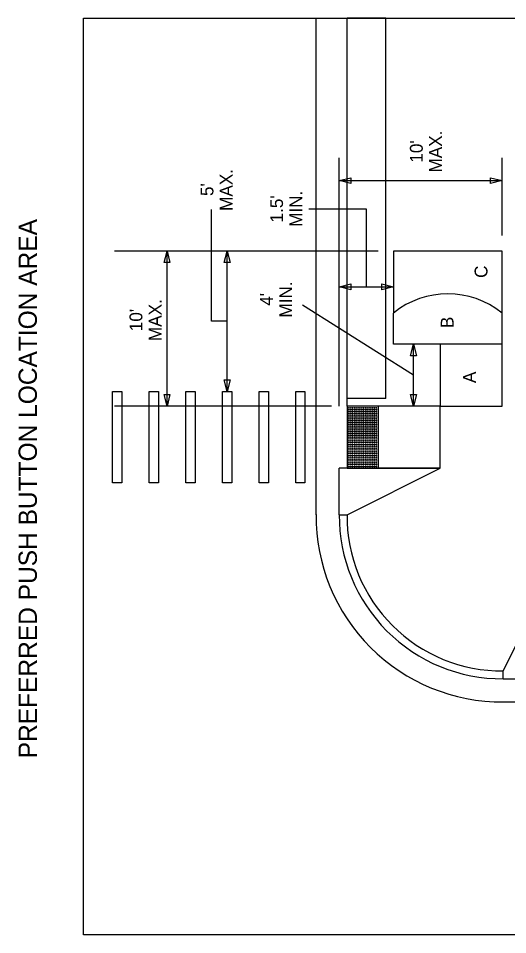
# Model space of a CAD drawing. Extents: x 610558 to 611161, y 419194 to 420064.
# Drawn here: x 610651.8 to 610812, y 419194 to 419494 of the extents above; entities that cross this region are included whole.
import ezdxf

# ---------------------------------------------------------------- set-up
doc = ezdxf.new("R2010")
doc.units = 0
doc.layers.add('Level 10', color=7, linetype='Continuous')

msp = doc.modelspace()

# ---------------------------------------------------------------- linework, layer by layer
at = {"layer": 'Level 10'}
for p, q in [((610673.08, 419194.01), (610673.08, 419494.01)), ((610673.08, 419494.01), (610962.92, 419494.01)), ((610749.26, 419331.49), (610749.26, 419494.01)), ((610759.42, 419367.04), (610759.42, 419494.01)), ((610772.11, 419494.01), (610759.42, 419494.01)), ((610772.11, 419369.58), (610772.11, 419494.01)), ((610756.88, 419367.04), (610756.88, 419448.3)), ((610810.2, 419422.91), (610810.2, 419448.3)), ((610756.88, 419440.88), (610810.2, 419440.88)), ((610769.57, 419417.83), (610683.24, 419417.83)), ((610700.47, 419367.04), (610700.47, 419417.83)), ((610720.15, 419371.89), (610720.15, 419417.83)), ((610810.2, 419397.52), (610810.2, 419417.83)), ((610756.88, 419406.09), (610774.65, 419406.09)), ((610781.18, 419377.2), (610744.87, 419400.08)), ((610774.65, 419387.36), (610774.65, 419397.52)), ((610810.2, 419387.36), (610810.2, 419397.52)), ((610810.2, 419387.36), (610774.65, 419387.36)), ((610781.18, 419367.04), (610781.18, 419387.36)), ((610754.34, 419367.04), (610683.24, 419367.04)), ((610772.11, 419369.58), (610759.42, 419369.58)), ((610789.89, 419367.04), (610759.42, 419367.04)), ((610759.42, 419367.04), (610759.42, 419346.73)), ((610769.57, 419367.04), (610769.57, 419346.73)), ((610789.89, 419346.73), (610789.89, 419367.04)), ((610789.89, 419346.73), (610756.88, 419346.73)), ((610756.88, 419331.49), (610756.88, 419346.73)), ((610759.42, 419346.73), (610789.89, 419346.73)), ((610759.42, 419331.49), (610789.89, 419346.73)), ((610756.88, 419331.49), (610759.42, 419331.49)), ((610810.56, 419280.35), (610825.8, 419310.82)), ((610810.56, 419277.81), (610810.56, 419280.35)), ((610810.56, 419277.81), (610825.8, 419277.81)), ((610810.56, 419270.19), (610861.35, 419270.19)), ((610962.92, 419194.01), (610673.08, 419194.01))]:
    msp.add_line(p, q, dxfattribs=at)
for points in [[(610760.69, 419439.93), (610756.88, 419440.88), (610760.69, 419441.83)], [(610806.39, 419441.83), (610810.2, 419440.88), (610806.39, 419439.93)], [(610699.52, 419414.02), (610700.47, 419417.83), (610701.43, 419414.02)], [(610719.2, 419414.02), (610720.15, 419417.83), (610721.1, 419414.02)], [(610760.69, 419405.14), (610756.88, 419406.09), (610760.69, 419407.04)], [(610770.84, 419407.04), (610774.65, 419406.09), (610770.84, 419405.14)], [(610780.22, 419383.55), (610781.18, 419387.36), (610782.13, 419383.55)], [(610789.89, 419367.04), (610810.2, 419367.04), (610810.2, 419387.36), (610789.89, 419387.36)], [(610721.1, 419375.7), (610720.15, 419371.89), (610719.2, 419375.7)], [(610682.65, 419371.89), (610685.65, 419371.89), (610685.65, 419341.89), (610682.65, 419341.89)], [(610694.65, 419371.89), (610697.65, 419371.89), (610697.65, 419341.89), (610694.65, 419341.89)], [(610701.43, 419370.85), (610700.47, 419367.04), (610699.52, 419370.85)], [(610706.65, 419371.89), (610709.65, 419371.89), (610709.65, 419341.89), (610706.65, 419341.89)], [(610718.65, 419371.89), (610721.65, 419371.89), (610721.65, 419341.89), (610718.65, 419341.89)], [(610730.65, 419371.89), (610733.65, 419371.89), (610733.65, 419341.89), (610730.65, 419341.89)], [(610742.65, 419371.89), (610745.65, 419371.89), (610745.65, 419341.89), (610742.65, 419341.89)], [(610782.13, 419370.85), (610781.18, 419367.04), (610780.22, 419370.85)]]:
    msp.add_lwpolyline(points, close=True, dxfattribs=at)
for points in [[(610720.15, 419394.86), (610715.07, 419394.86), (610715.07, 419431.4)], [(610765.76, 419406.09), (610765.76, 419431.48), (610746.86, 419431.48)], [(610810.2, 419417.83), (610774.65, 419417.83), (610774.65, 419397.52)]]:
    msp.add_lwpolyline(points, dxfattribs=at)
for centre in [(610760.02, 419366.49), (610760.02, 419365.89), (610760.02, 419365.29), (610760.02, 419364.69), (610760.02, 419364.09), (610760.62, 419366.49), (610760.62, 419365.89), (610760.62, 419365.29), (610760.62, 419364.69), (610760.62, 419364.09), (610761.22, 419366.49), (610761.22, 419365.89), (610761.22, 419365.29), (610761.22, 419364.69), (610761.22, 419364.09), (610761.82, 419366.49), (610761.82, 419365.89), (610761.82, 419365.29), (610761.82, 419364.69), (610761.82, 419364.09), (610762.42, 419366.49), (610762.42, 419365.89), (610762.42, 419365.29), (610762.42, 419364.69), (610762.42, 419364.09), (610763.02, 419366.49), (610763.02, 419365.89), (610763.02, 419365.29), (610763.02, 419364.69), (610763.02, 419364.09), (610763.62, 419366.49), (610763.62, 419365.89), (610763.62, 419365.29), (610763.62, 419364.69), (610763.62, 419364.09), (610764.22, 419366.49), (610764.22, 419365.89), (610764.22, 419365.29), (610764.22, 419364.69), (610764.22, 419364.09), (610764.82, 419366.49), (610764.82, 419365.89), (610764.82, 419365.29), (610764.82, 419364.69), (610764.82, 419364.09), (610765.42, 419366.49), (610765.42, 419365.89), (610765.42, 419365.29), (610765.42, 419364.69), (610765.42, 419364.09), (610766.02, 419366.49), (610766.02, 419365.89), (610766.02, 419365.29), (610766.02, 419364.69), (610766.02, 419364.09), (610766.62, 419366.49), (610766.62, 419365.89), (610766.62, 419365.29), (610766.62, 419364.69), (610766.62, 419364.09), (610767.22, 419366.49), (610767.22, 419365.89), (610767.22, 419365.29), (610767.22, 419364.69), (610767.22, 419364.09), (610767.82, 419366.49), (610767.82, 419365.89), (610767.82, 419365.29), (610767.82, 419364.69), (610767.82, 419364.09), (610768.42, 419366.49), (610768.42, 419365.89), (610768.42, 419365.29), (610768.42, 419364.69), (610768.42, 419364.09), (610769.02, 419366.49), (610769.02, 419365.89), (610769.02, 419365.29), (610769.02, 419364.69), (610769.02, 419364.09), (610760.02, 419363.49), (610760.02, 419362.89), (610760.02, 419362.29), (610760.02, 419361.69), (610760.02, 419361.09), (610760.62, 419363.49), (610760.62, 419362.89), (610760.62, 419362.29), (610760.62, 419361.69), (610760.62, 419361.09), (610761.22, 419363.49), (610761.22, 419362.89), (610761.22, 419362.29), (610761.22, 419361.69), (610761.22, 419361.09), (610761.82, 419363.49), (610761.82, 419362.89), (610761.82, 419362.29), (610761.82, 419361.69), (610761.82, 419361.09), (610762.42, 419363.49), (610762.42, 419362.89), (610762.42, 419362.29), (610762.42, 419361.69), (610762.42, 419361.09), (610763.02, 419363.49), (610763.02, 419362.89), (610763.02, 419362.29), (610763.02, 419361.69), (610763.02, 419361.09), (610763.62, 419363.49), (610763.62, 419362.89), (610763.62, 419362.29), (610763.62, 419361.69), (610763.62, 419361.09), (610764.22, 419363.49), (610764.22, 419362.89), (610764.22, 419362.29), (610764.22, 419361.69), (610764.22, 419361.09), (610764.82, 419363.49), (610764.82, 419362.89), (610764.82, 419362.29), (610764.82, 419361.69), (610764.82, 419361.09), (610765.42, 419363.49), (610765.42, 419362.89), (610765.42, 419362.29), (610765.42, 419361.69), (610765.42, 419361.09), (610766.02, 419363.49), (610766.02, 419362.89), (610766.02, 419362.29), (610766.02, 419361.69), (610766.02, 419361.09), (610766.62, 419363.49), (610766.62, 419362.89), (610766.62, 419362.29), (610766.62, 419361.69), (610766.62, 419361.09), (610767.22, 419363.49), (610767.22, 419362.89), (610767.22, 419362.29), (610767.22, 419361.69), (610767.22, 419361.09), (610767.82, 419363.49), (610767.82, 419362.89), (610767.82, 419362.29), (610767.82, 419361.69), (610767.82, 419361.09), (610768.42, 419363.49), (610768.42, 419362.89), (610768.42, 419362.29), (610768.42, 419361.69), (610768.42, 419361.09), (610769.02, 419363.49), (610769.02, 419362.89), (610769.02, 419362.29), (610769.02, 419361.69), (610769.02, 419361.09), (610760.02, 419360.49), (610760.02, 419359.89), (610760.02, 419359.29), (610760.02, 419358.69), (610760.02, 419358.09), (610760.62, 419360.49), (610760.62, 419359.89), (610760.62, 419359.29), (610760.62, 419358.69), (610760.62, 419358.09), (610761.22, 419360.49), (610761.22, 419359.89), (610761.22, 419359.29), (610761.22, 419358.69), (610761.22, 419358.09), (610761.82, 419360.49), (610761.82, 419359.89), (610761.82, 419359.29), (610761.82, 419358.69), (610761.82, 419358.09), (610762.42, 419360.49), (610762.42, 419359.89), (610762.42, 419359.29), (610762.42, 419358.69), (610762.42, 419358.09), (610763.02, 419360.49), (610763.02, 419359.89), (610763.02, 419359.29), (610763.02, 419358.69), (610763.02, 419358.09), (610763.62, 419360.49), (610763.62, 419359.89), (610763.62, 419359.29), (610763.62, 419358.69), (610763.62, 419358.09), (610764.22, 419360.49), (610764.22, 419359.89), (610764.22, 419359.29), (610764.22, 419358.69), (610764.22, 419358.09), (610764.82, 419360.49), (610764.82, 419359.89), (610764.82, 419359.29), (610764.82, 419358.69), (610764.82, 419358.09), (610765.42, 419360.49), (610765.42, 419359.89), (610765.42, 419359.29), (610765.42, 419358.69), (610765.42, 419358.09), (610766.02, 419360.49), (610766.02, 419359.89), (610766.02, 419359.29), (610766.02, 419358.69), (610766.02, 419358.09), (610766.62, 419360.49), (610766.62, 419359.89), (610766.62, 419359.29), (610766.62, 419358.69), (610766.62, 419358.09), (610767.22, 419360.49), (610767.22, 419359.89), (610767.22, 419359.29), (610767.22, 419358.69), (610767.22, 419358.09), (610767.82, 419360.49), (610767.82, 419359.89), (610767.82, 419359.29), (610767.82, 419358.69), (610767.82, 419358.09), (610768.42, 419360.49), (610768.42, 419359.89), (610768.42, 419359.29), (610768.42, 419358.69), (610768.42, 419358.09), (610769.02, 419360.49), (610769.02, 419359.89), (610769.02, 419359.29), (610769.02, 419358.69), (610769.02, 419358.09), (610760.02, 419357.49), (610760.02, 419356.89), (610760.02, 419356.29), (610760.02, 419355.69), (610760.02, 419355.09), (610760.62, 419357.49), (610760.62, 419356.89), (610760.62, 419356.29), (610760.62, 419355.69), (610760.62, 419355.09), (610761.22, 419357.49), (610761.22, 419356.89), (610761.22, 419356.29), (610761.22, 419355.69), (610761.22, 419355.09), (610761.82, 419357.49), (610761.82, 419356.89), (610761.82, 419356.29), (610761.82, 419355.69), (610761.82, 419355.09), (610762.42, 419357.49), (610762.42, 419356.89), (610762.42, 419356.29), (610762.42, 419355.69), (610762.42, 419355.09), (610763.02, 419357.49), (610763.02, 419356.89), (610763.02, 419356.29), (610763.02, 419355.69), (610763.02, 419355.09), (610763.62, 419357.49), (610763.62, 419356.89), (610763.62, 419356.29), (610763.62, 419355.69), (610763.62, 419355.09), (610764.22, 419357.49), (610764.22, 419356.89), (610764.22, 419356.29), (610764.22, 419355.69), (610764.22, 419355.09), (610764.82, 419357.49), (610764.82, 419356.89), (610764.82, 419356.29), (610764.82, 419355.69), (610764.82, 419355.09), (610765.42, 419357.49), (610765.42, 419356.89), (610765.42, 419356.29), (610765.42, 419355.69), (610765.42, 419355.09), (610766.02, 419357.49), (610766.02, 419356.89), (610766.02, 419356.29), (610766.02, 419355.69), (610766.02, 419355.09), (610766.62, 419357.49), (610766.62, 419356.89), (610766.62, 419356.29), (610766.62, 419355.69), (610766.62, 419355.09), (610767.22, 419357.49), (610767.22, 419356.89), (610767.22, 419356.29), (610767.22, 419355.69), (610767.22, 419355.09), (610767.82, 419357.49), (610767.82, 419356.89), (610767.82, 419356.29), (610767.82, 419355.69), (610767.82, 419355.09), (610768.42, 419357.49), (610768.42, 419356.89), (610768.42, 419356.29), (610768.42, 419355.69), (610768.42, 419355.09), (610769.02, 419357.49), (610769.02, 419356.89), (610769.02, 419356.29), (610769.02, 419355.69), (610769.02, 419355.09), (610760.02, 419354.49), (610760.02, 419353.89), (610760.02, 419353.29), (610760.02, 419352.69), (610760.02, 419352.09), (610760.62, 419354.49), (610760.62, 419353.89), (610760.62, 419353.29), (610760.62, 419352.69), (610760.62, 419352.09), (610761.22, 419354.49), (610761.22, 419353.89), (610761.22, 419353.29), (610761.22, 419352.69), (610761.22, 419352.09), (610761.82, 419354.49), (610761.82, 419353.89), (610761.82, 419353.29), (610761.82, 419352.69), (610761.82, 419352.09), (610762.42, 419354.49), (610762.42, 419353.89), (610762.42, 419353.29), (610762.42, 419352.69), (610762.42, 419352.09), (610763.02, 419354.49), (610763.02, 419353.89), (610763.02, 419353.29), (610763.02, 419352.69), (610763.02, 419352.09), (610763.62, 419354.49), (610763.62, 419353.89), (610763.62, 419353.29), (610763.62, 419352.69), (610763.62, 419352.09), (610764.22, 419354.49), (610764.22, 419353.89), (610764.22, 419353.29), (610764.22, 419352.69), (610764.22, 419352.09), (610764.82, 419354.49), (610764.82, 419353.89), (610764.82, 419353.29), (610764.82, 419352.69), (610764.82, 419352.09), (610765.42, 419354.49), (610765.42, 419353.89), (610765.42, 419353.29), (610765.42, 419352.69), (610765.42, 419352.09), (610766.02, 419354.49), (610766.02, 419353.89), (610766.02, 419353.29), (610766.02, 419352.69), (610766.02, 419352.09), (610766.62, 419354.49), (610766.62, 419353.89), (610766.62, 419353.29), (610766.62, 419352.69), (610766.62, 419352.09), (610767.22, 419354.49), (610767.22, 419353.89), (610767.22, 419353.29), (610767.22, 419352.69), (610767.22, 419352.09), (610767.82, 419354.49), (610767.82, 419353.89), (610767.82, 419353.29), (610767.82, 419352.69), (610767.82, 419352.09), (610768.42, 419354.49), (610768.42, 419353.89), (610768.42, 419353.29), (610768.42, 419352.69), (610768.42, 419352.09), (610769.02, 419354.49), (610769.02, 419353.89), (610769.02, 419353.29), (610769.02, 419352.69), (610769.02, 419352.09), (610760.02, 419351.49), (610760.02, 419350.89), (610760.02, 419350.29), (610760.02, 419349.69), (610760.02, 419349.09), (610760.62, 419351.49), (610760.62, 419350.89), (610760.62, 419350.29), (610760.62, 419349.69), (610760.62, 419349.09), (610761.22, 419351.49), (610761.22, 419350.89), (610761.22, 419350.29), (610761.22, 419349.69), (610761.22, 419349.09), (610761.82, 419351.49), (610761.82, 419350.89), (610761.82, 419350.29), (610761.82, 419349.69), (610761.82, 419349.09), (610762.42, 419351.49), (610762.42, 419350.89), (610762.42, 419350.29), (610762.42, 419349.69), (610762.42, 419349.09), (610763.02, 419351.49), (610763.02, 419350.89), (610763.02, 419350.29), (610763.02, 419349.69), (610763.02, 419349.09), (610763.62, 419351.49), (610763.62, 419350.89), (610763.62, 419350.29), (610763.62, 419349.69), (610763.62, 419349.09), (610764.22, 419351.49), (610764.22, 419350.89), (610764.22, 419350.29), (610764.22, 419349.69), (610764.22, 419349.09), (610764.82, 419351.49), (610764.82, 419350.89), (610764.82, 419350.29), (610764.82, 419349.69), (610764.82, 419349.09), (610765.42, 419351.49), (610765.42, 419350.89), (610765.42, 419350.29), (610765.42, 419349.69), (610765.42, 419349.09), (610766.02, 419351.49), (610766.02, 419350.89), (610766.02, 419350.29), (610766.02, 419349.69), (610766.02, 419349.09), (610766.62, 419351.49), (610766.62, 419350.89), (610766.62, 419350.29), (610766.62, 419349.69), (610766.62, 419349.09), (610767.22, 419351.49), (610767.22, 419350.89), (610767.22, 419350.29), (610767.22, 419349.69), (610767.22, 419349.09), (610767.82, 419351.49), (610767.82, 419350.89), (610767.82, 419350.29), (610767.82, 419349.69), (610767.82, 419349.09), (610768.42, 419351.49), (610768.42, 419350.89), (610768.42, 419350.29), (610768.42, 419349.69), (610768.42, 419349.09), (610769.02, 419351.49), (610769.02, 419350.89), (610769.02, 419350.29), (610769.02, 419349.69), (610769.02, 419349.09), (610760.02, 419348.49), (610760.02, 419347.89), (610760.02, 419347.29), (610760.62, 419348.49), (610760.62, 419347.89), (610760.62, 419347.29), (610761.22, 419348.49), (610761.22, 419347.89), (610761.22, 419347.29), (610761.82, 419348.49), (610761.82, 419347.89), (610761.82, 419347.29), (610762.42, 419348.49), (610762.42, 419347.89), (610762.42, 419347.29), (610763.02, 419348.49), (610763.02, 419347.89), (610763.02, 419347.29), (610763.62, 419348.49), (610763.62, 419347.89), (610763.62, 419347.29), (610764.22, 419348.49), (610764.22, 419347.89), (610764.22, 419347.29), (610764.82, 419348.49), (610764.82, 419347.89), (610764.82, 419347.29), (610765.42, 419348.49), (610765.42, 419347.89), (610765.42, 419347.29), (610766.02, 419348.49), (610766.02, 419347.89), (610766.02, 419347.29), (610766.62, 419348.49), (610766.62, 419347.89), (610766.62, 419347.29), (610767.22, 419348.49), (610767.22, 419347.89), (610767.22, 419347.29), (610767.82, 419348.49), (610767.82, 419347.89), (610767.82, 419347.29), (610768.42, 419348.49), (610768.42, 419347.89), (610768.42, 419347.29), (610769.02, 419348.49), (610769.02, 419347.89), (610769.02, 419347.29)]:
    msp.add_circle(centre, 0.112, dxfattribs=at)
for centre, radius, start, end in [((610792.43, 419375.61), 28.21, 50.9422, 129.0578), ((610810.2, 419331.13), 60.94, 179.5914, 270.4086), ((610810.2, 419331.13), 53.33, 179.5914, 270.4086), ((610810.2, 419331.13), 50.79, 179.5914, 270.4086)]:
    msp.add_arc(centre, radius, start, end, dxfattribs=at)

# ---------------------------------------------------------------- texts
for s, height, p in [('MAX.', 4.2, (610790.52, 419443.52)), ("10'", 4.2, (610784.22, 419446.75)), ('MAX.', 4.2, (610721.95, 419430.96)), ("5'", 4.2, (610715.65, 419435.83)), ('MIN.', 4.2, (610744.75, 419425.73)), ("1.5'", 4.2, (610738.45, 419427.17)), ('PREFERRED PUSH BUTTON LOCATION AREA', 6, (610657.84, 419251.76)), ('C', 4.2, (610805.42, 419409.02)), ('MIN.', 4.2, (610741.45, 419396.03)), ("4'", 4.2, (610735.15, 419399.91)), ('MAX.', 4.2, (610698.68, 419388.33)), ("10'", 4.2, (610692.38, 419391.57)), ('B', 4.2, (610794.32, 419392.58)), ('A', 4.2, (610801.62, 419374.6))]:
    msp.add_text(s, height=height, rotation=90, dxfattribs=at).set_placement(p)

doc.saveas('drawing.dxf')
